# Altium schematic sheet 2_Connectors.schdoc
size 431 x 309 mm; Symbol: Sheet-Symbol_A4; Device: Sheet-Symbol_A4; Company: EasyEDA.com; Drawed: EasyEDA Pro; Reviewed: EasyEDA Pro; Version: V0.1; Page Size: A4; @Project Name: CM4-Nvme-NAS-main; @Page Count: 6; @Update Date: 2023-05-19; @Create Date: 2023-04-29; @Schematic Name: RaspberryPiNVMeNAS; Part Number: JLCPCB-002; @Page No: 5; @Page Name: Connectors
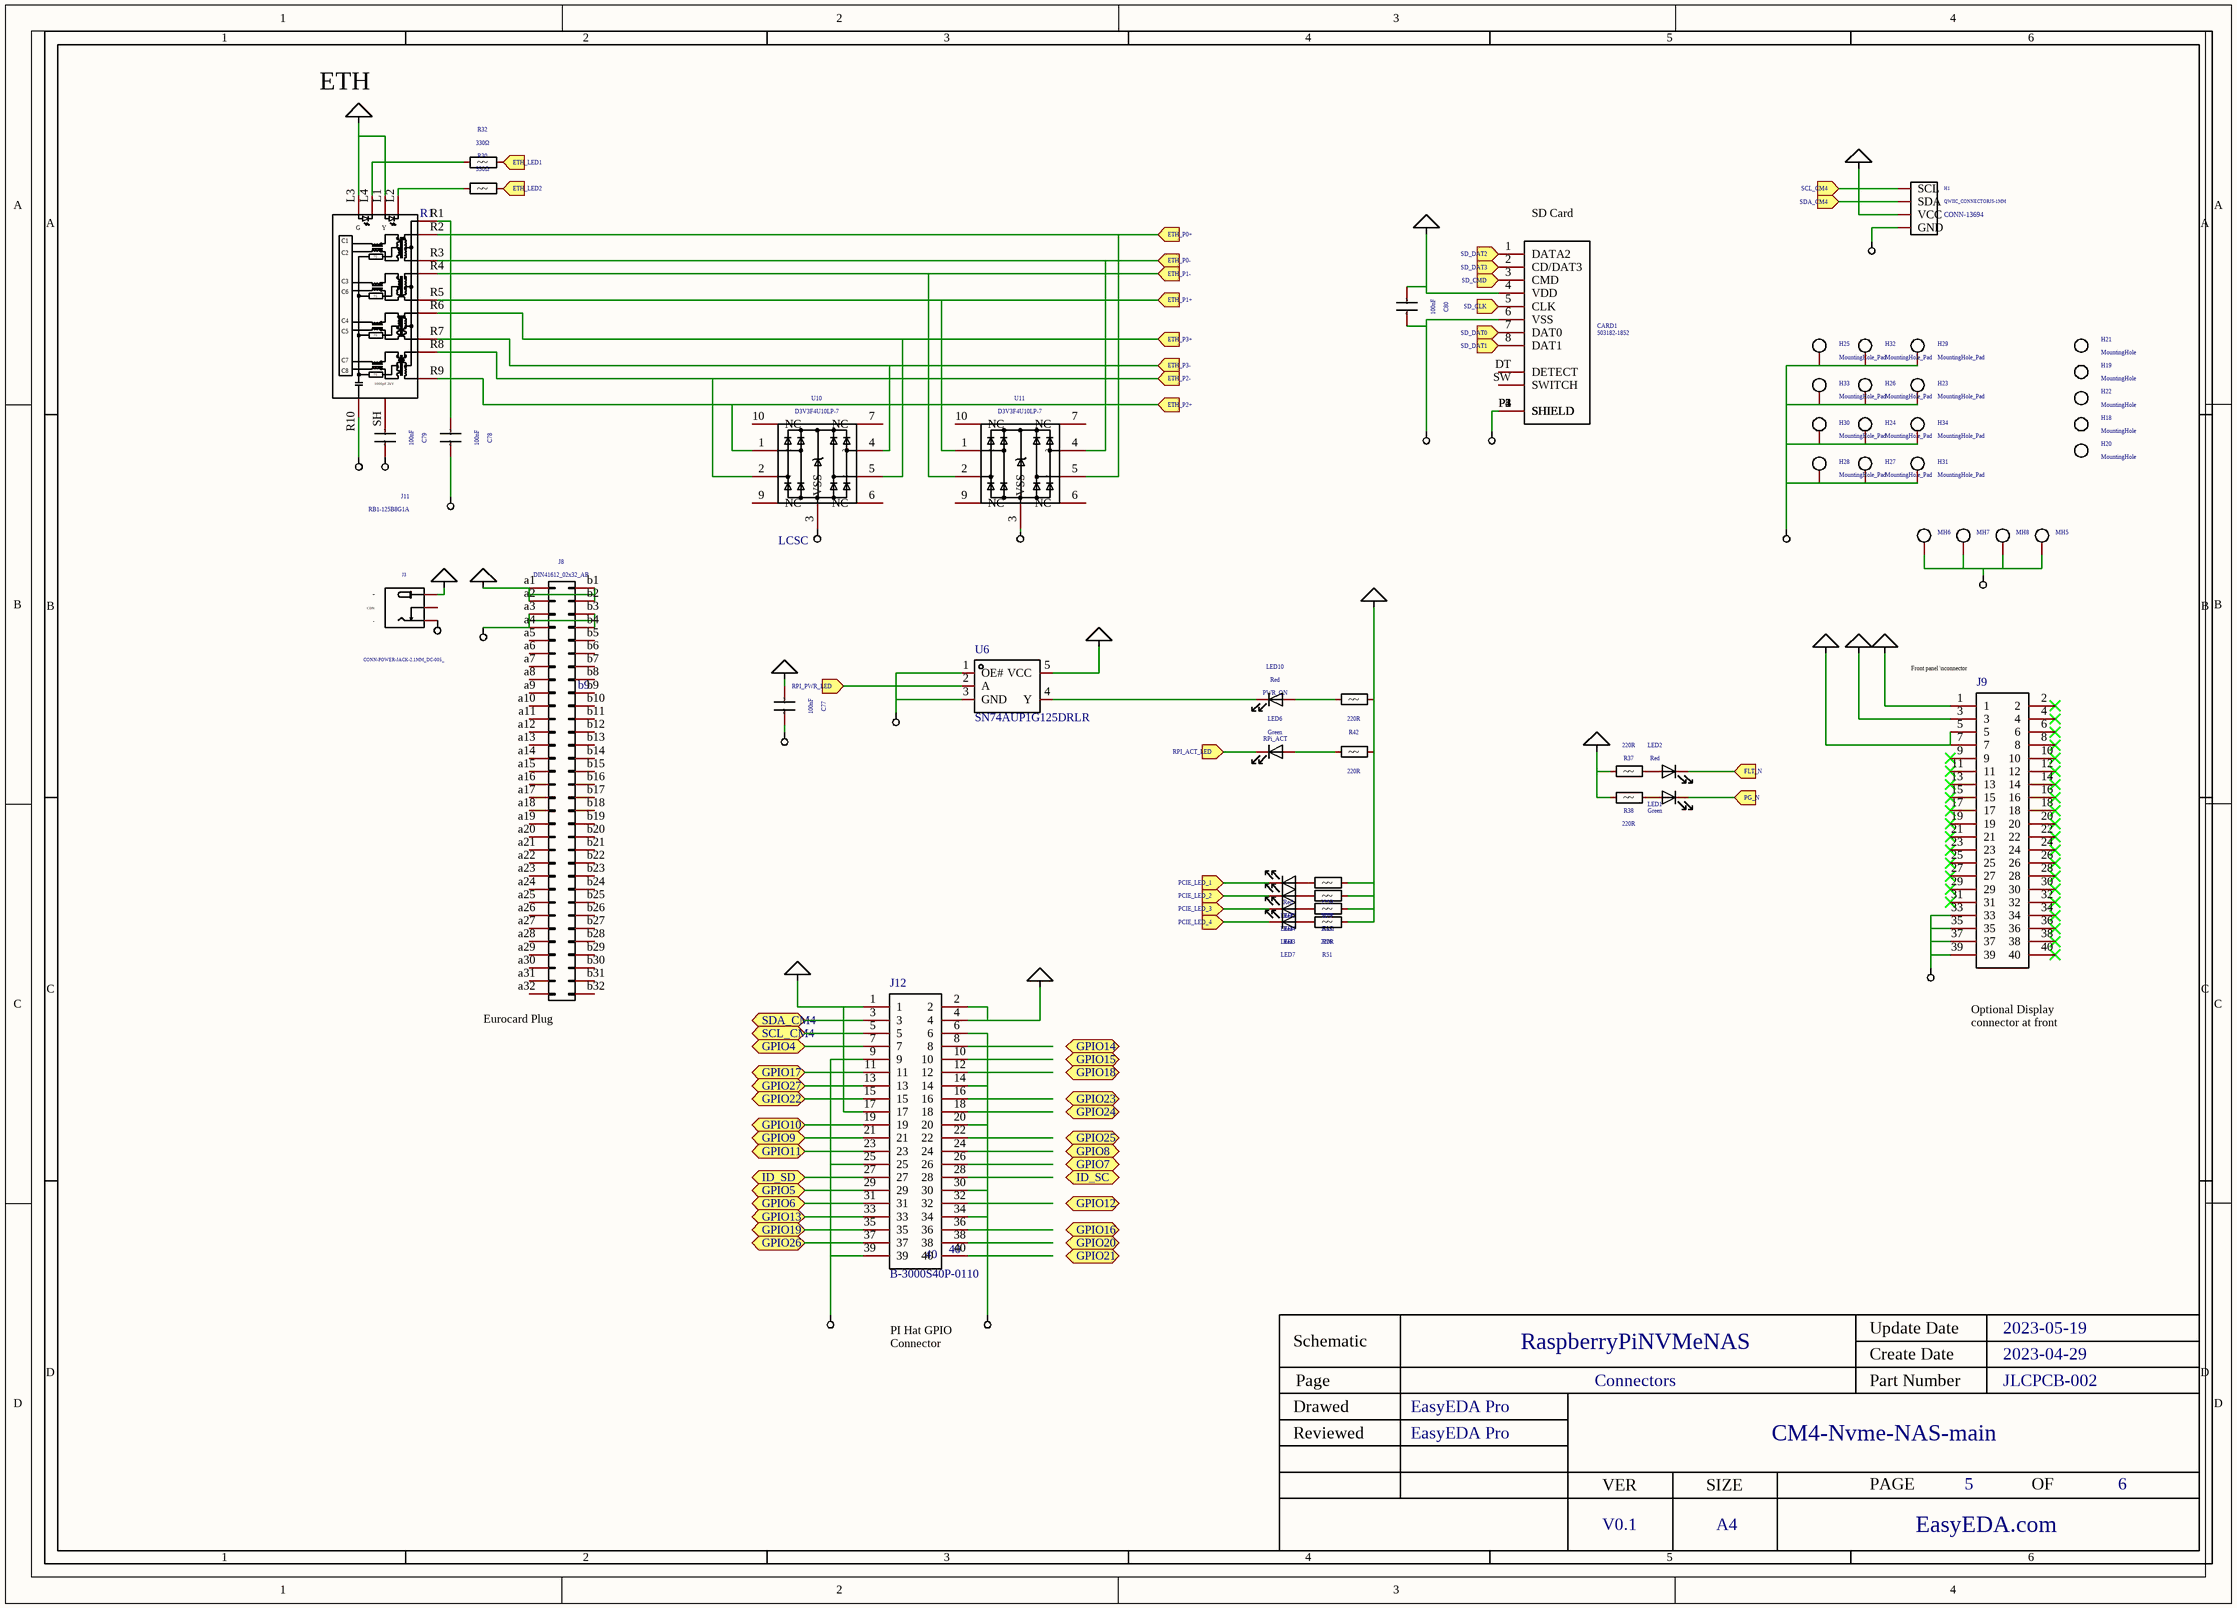
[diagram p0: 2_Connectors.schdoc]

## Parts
C77  100nF  [C0402]
C78  100nF  [C0402]
C79  100nF  [C0402]
C80  100nF  [C0402]
CARD1  value 503182-1852  [TF-SMD_503398-1892]  (hidden comment: 5033981892)
H1  value QWIIC_CONNECTORJS-1MM  Field4: CONN-13694  [HDR-SMD_4P-P2.00-H-M-W6.0-N]  (hidden comment: X4611WRS-04I-C40D28)
H18  value MountingHole  [MountingHole:MountingHole_2.7mm_M2.5]  (hidden comment: Mechanical_MountingHole)
H19  value MountingHole  [MountingHole:MountingHole_2.7mm_M2.5]  (hidden comment: Mechanical_MountingHole)
H20  value MountingHole  [MountingHole:MountingHole_2.7mm_M2.5]  (hidden comment: Mechanical_MountingHole)
H21  value MountingHole  [MountingHole:MountingHole_2.7mm_M2.5]  (hidden comment: Mechanical_MountingHole)
H22  value MountingHole  [MountingHole:MountingHole_2.7mm_M2.5]  (hidden comment: Mechanical_MountingHole)
H23  value MountingHole_Pad  [MountingHole:MountingHole_2.7mm_M2.5_Pad_TopOnly]  (hidden comment: Mechanical_MountingHole_Pad)
H24  value MountingHole_Pad  [MountingHole:MountingHole_2.7mm_M2.5_Pad_TopOnly]  (hidden comment: Mechanical_MountingHole_Pad)
H25  value MountingHole_Pad  [MountingHole:MountingHole_2.7mm_M2.5_Pad_TopOnly]  (hidden comment: Mechanical_MountingHole_Pad)
H26  value MountingHole_Pad  [MountingHole:MountingHole_2.7mm_M2.5_Pad_TopOnly]  (hidden comment: Mechanical_MountingHole_Pad)
H27  value MountingHole_Pad  [MountingHole:MountingHole_2.7mm_M2.5_Pad_TopOnly]  (hidden comment: Mechanical_MountingHole_Pad)
H28  value MountingHole_Pad  [MountingHole:MountingHole_2.7mm_M2.5_Pad_TopOnly]  (hidden comment: Mechanical_MountingHole_Pad)
H29  value MountingHole_Pad  [MountingHole:MountingHole_2.7mm_M2.5_Pad_TopOnly]  (hidden comment: Mechanical_MountingHole_Pad)
H30  value MountingHole_Pad  [MountingHole:MountingHole_2.7mm_M2.5_Pad_TopOnly]  (hidden comment: Mechanical_MountingHole_Pad)
H31  value MountingHole_Pad  [MountingHole:MountingHole_2.7mm_M2.5_Pad_TopOnly]  (hidden comment: Mechanical_MountingHole_Pad)
H32  value MountingHole_Pad  [MountingHole:MountingHole_2.7mm_M2.5_Pad_TopOnly]  (hidden comment: Mechanical_MountingHole_Pad)
H33  value MountingHole_Pad  [MountingHole:MountingHole_2.7mm_M2.5_Pad_TopOnly]  (hidden comment: Mechanical_MountingHole_Pad)
H34  value MountingHole_Pad  [MountingHole:MountingHole_2.7mm_M2.5_Pad_TopOnly]  (hidden comment: Mechanical_MountingHole_Pad)
J3  value CONN-POWER-JACK-2.1MM_DC-005_  [OPL_Connector:DCJ3P-11.6X9.6X7.0MM]  (hidden comment: OPL_Connector_CONN-POWER-JACK-2.1MM_DC-005_)
J8  value DIN41612_02x32_AB  NUMBER: b9  (hidden comment: Connector_DIN41612_02x32_AB)
J9  B-3000S40P-0110  [CONN-TH_300S-40P]  (value not drawn)
J11  value RB1-125B8G1A  NUMBER: R1  [RJ45-TH_HR911105A]  (hidden comment: HR911105A)
J12  NAME: 40  [CONN-TH_300S-40P]  (hidden comment: B-3000S40P-0110)
LED1  value Green  [LED0603-RD_RED]  (hidden comment: NCD0603R1)
LED2  value Red  [LED0603-RD_RED]  (hidden comment: NCD0603R1)
LED3  value Red  [LED0603-RD_RED]  (hidden comment: NCD0603R1)
LED4  value Red  [LED0603-RD_RED]  (hidden comment: NCD0603R1)
LED5  value Red  [LED0603-RD_RED]  (hidden comment: NCD0603R1)
LED6  value Green  [LED0603-RD_RED]  (hidden comment: RPi_ACT)
LED7  value Red  [LED0603-RD_RED]  (hidden comment: NCD0603R1)
LED10  value Red  [LED0603-RD_RED]  (hidden comment: PWR_ON)
MH5  Mechanical_MountingHole_Pad  (value not drawn)
MH6  Mechanical_MountingHole_Pad  (value not drawn)
MH7  Mechanical_MountingHole_Pad  (value not drawn)
MH8  Mechanical_MountingHole_Pad  (value not drawn)
R26  10kΩ  [R0402]
R30  330Ω  [R0402]
R32  330Ω  [R0402]
R37  value 220R  [Resistor_SMD:R_0402_1005Metric]  (hidden comment: Device_R)
R38  value 220R  [Resistor_SMD:R_0402_1005Metric]  (hidden comment: Device_R)
R39  value 220R  [Resistor_SMD:R_0402_1005Metric]  (hidden comment: Device_R)
R42  value 220R  [Resistor_SMD:R_0402_1005Metric]  (hidden comment: Device_R)
R51  value 220R  [Resistor_SMD:R_0402_1005Metric]  (hidden comment: Device_R)
R70  value 220R  [Resistor_SMD:R_0402_1005Metric]  (hidden comment: Device_R)
R73  value 220R  [Resistor_SMD:R_0402_1005Metric]  (hidden comment: Device_R)
U6  SN74AUP1G125DRLR  [SOT-553-5_L1.6-W1.2-P0.50-LS1.6-BL]
U10  value D3V3F4U10LP-7  Supplier: LCSC  [Package_DFN_QFN:Diodes_UDFN-10_1.0x2.5mm_P0.5mm]  (hidden comment: Power_Protection_D3V3XA4B10LP)
U11  value D3V3F4U10LP-7  [Package_DFN_QFN:Diodes_UDFN-10_1.0x2.5mm_P0.5mm]  (hidden comment: Power_Protection_D3V3XA4B10LP)

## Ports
ETH_LED1 (in), ETH_LED2 (in), ETH_P0+ (in), ETH_P0- (in), ETH_P1+ (in), ETH_P1- (in), ETH_P2+ (in), ETH_P2- (in), ETH_P3+ (in), ETH_P3- (in), FLT_N (in), GPIO4 (bidir), GPIO5 (bidir), GPIO6 (bidir), GPIO7 (bidir), GPIO8 (bidir), GPIO9 (bidir), GPIO10 (bidir), GPIO11 (bidir), GPIO12 (bidir), GPIO13 (bidir), GPIO14 (bidir), GPIO15 (bidir), GPIO16 (bidir), GPIO17 (bidir), GPIO18 (bidir), GPIO19 (bidir), GPIO20 (bidir), GPIO21 (bidir), GPIO22 (bidir), GPIO23 (bidir), GPIO24 (bidir), GPIO25 (bidir), GPIO26 (bidir), GPIO27 (bidir), ID_SC (bidir), ID_SD (bidir), PCIE_LED_1 (in), PCIE_LED_2 (in), PCIE_LED_3 (in), PCIE_LED_4 (in), PG_N (in), RPI_ACT_LED (in), RPI_PWR_LED (in), SCL_CM4 (bidir), SCL_CM4 (in), SD_CLK (in), SD_CMD (in), SD_DAT0 (in), SD_DAT1 (in), SD_DAT2 (in), SD_DAT3 (in), SDA_CM4 (bidir), SDA_CM4 (in)

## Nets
GND: J3.2(-) J8.a3(Pin_a3) J8.a4(Pin_a4) J8.b3(Pin_b3) J8.b4(Pin_b4) U11.3(VSS) U11.8(VSS)
POWER_+3.3V: C77.1 C80.1 CARD1.4(VDD) H1.2(VCC) J9.5 J9.7 J11.L1 J11.L3 J12.1 J12.17 R26.2 R39.2 R42.1 R51.2 R70.1 R73.2 U6.5(VCC)
POWER_+5V: J9.3 J12.2 J12.4
POWER_+12P: J3.1(+) J8.a1(Pin_a1) J8.a2(Pin_a2) J8.b1(Pin_b1) J8.b2(Pin_b2)
POWER_+12V: J9.1 R37.1 R38.1
POWER_GND: C77.2 C78.2 C79.2 C80.2 CARD1.6(VSS) CARD1.P1(SHIELD) CARD1.P2(SHIELD) CARD1.P3(SHIELD) CARD1.P4(SHIELD) CARD1.P5(SHIELD) H1.1(GND) H23.1 H24.1 H25.1 H26.1 H27.1 H28.1 H29.1 H30.1 H31.1 H32.1 H33.1 H34.1 J9.33 J9.35 J9.37 J9.39 J11.R10(GND) J12.6 J12.9 J12.14 J12.20 J12.25 J12.30 J12.34 J12.39 MH5.1 MH6.1 MH7.1 MH8.1 U6.1(OE#) U6.3(GND) U10.3(VSS) U10.8(VSS)
ETH_LED1: R32.2 ; port ETH_LED1
ETH_LED2: R30.2 ; port ETH_LED2
ETH_P0+: J11.R2(TD1+) U11.5 ; port ETH_P0+
ETH_P0-: J11.R3(TD1-) U11.4 ; port ETH_P0-
ETH_P1+: J11.R5(TD2-) U11.1 ; port ETH_P1+
ETH_P1-: J11.R4(TD2+) U11.2 ; port ETH_P1-
ETH_P2+: J11.R9(TD4-) U10.1 ; port ETH_P2+
ETH_P2-: J11.R8(TD4+) U10.2 ; port ETH_P2-
ETH_P3+: J11.R6(TD3+) U10.5 ; port ETH_P3+
ETH_P3-: J11.R7(TD3-) U10.4 ; port ETH_P3-
FLT_N: LED2.1(K) ; port FLT_N
GPIO4: J12.7 ; port GPIO4
GPIO5: J12.29 ; port GPIO5
GPIO6: J12.31 ; port GPIO6
GPIO9: J12.21 ; port GPIO9
GPIO10: J12.19 ; port GPIO10
GPIO11: J12.23 ; port GPIO11
GPIO13: J12.33 ; port GPIO13
GPIO17: J12.11 ; port GPIO17
GPIO19: J12.35 ; port GPIO19
GPIO22: J12.15 ; port GPIO22
GPIO26: J12.37 ; port GPIO26
GPIO27: J12.13 ; port GPIO27
ID_SD: J12.27 ; port ID_SD
PCIE_LED_1: LED5.1(K) ; port PCIE_LED_1
PCIE_LED_2: LED4.1(K) ; port PCIE_LED_2
PCIE_LED_3: LED3.1(K) ; port PCIE_LED_3
PCIE_LED_4: LED7.1(K) ; port PCIE_LED_4
PG_N: LED1.1(K) ; port PG_N
RPI_ACT_LED: LED6.1(K) ; port RPI_ACT_LED
RPI_PWR_LED: U6.2(A) ; port RPI_PWR_LED
SCL_CM4: H1.4(SCL) J12.5 ; port SCL_CM4
SD_CLK: CARD1.5(CLK) ; port SD_CLK
SD_CMD: CARD1.3(CMD) ; port SD_CMD
SD_DAT0: CARD1.7(DAT0) ; port SD_DAT0
SD_DAT1: CARD1.8(DAT1) ; port SD_DAT1
SD_DAT2: CARD1.1(DATA2) ; port SD_DAT2
SD_DAT3: CARD1.2(CD/DAT3) ; port SD_DAT3
SDA_CM4: H1.3(SDA) J12.3 ; port SDA_CM4
NetC78_1: C78.1 J11.R1(CT)
NetC79_1: C79.1 J11.SH
NetJ11_L2: J11.L2 R30.1
NetJ11_L4: J11.L4 R32.1
NetLED1_2: LED1.2(A) R38.2
NetLED2_2: LED2.2(A) R37.2
NetLED3_2: LED3.2(A) R26.1
NetLED4_2: LED4.2(A) R39.1
NetLED5_2: LED5.2(A) R73.1
NetLED6_2: LED6.2(A) R70.2
NetLED7_2: LED7.2(A) R51.1
NetLED10_1: LED10.1(K) U6.4(Y)
NetLED10_2: LED10.2(A) R42.2

Not connected (* = marked no-connect by the designer): CARD1 DT(DETECT) SW(SWITCH); J3 3(CDN); J8 a5(Pin_a5) a6(Pin_a6) a7(Pin_a7) a8(Pin_a8) a9(Pin_a9) a10(Pin_a10) a11(Pin_a11) a12(Pin_a12) a13(Pin_a13) a14(Pin_a14) a15(Pin_a15) a16(Pin_a16) a17(Pin_a17) a18(Pin_a18) a19(Pin_a19) a20(Pin_a20) a21(Pin_a21) a22(Pin_a22) a23(Pin_a23) a24(Pin_a24) a25(Pin_a25) a26(Pin_a26) a27(Pin_a27) a28(Pin_a28) a29(Pin_a29) a30(Pin_a30) a31(Pin_a31) a32(Pin_a32) b5(Pin_b5) b6(Pin_b6) b7(Pin_b7) b8(Pin_b8) b9(Pin_b9) b10(Pin_b10) b11(Pin_b11) b12(Pin_b12) b13(Pin_b13) b14(Pin_b14) b15(Pin_b15) b16(Pin_b16) b17(Pin_b17) b18(Pin_b18) b19(Pin_b19) b20(Pin_b20) b21(Pin_b21) b22(Pin_b22) b23(Pin_b23) b24(Pin_b24) b25(Pin_b25) b26(Pin_b26) b27(Pin_b27) b28(Pin_b28) b29(Pin_b29) b30(Pin_b30) b31(Pin_b31) b32(Pin_b32); J9 2* 4* 6* 8* 9* 10* 11* 12* 13* 14* 15* 16* 17* 18* 19* 20* 21* 22* 23* 24* 25* 26* 27* 28* 29* 30* 31* 32* 34* 36* 38* 40*; J12 8 10 12 16 18 22 24 26 28 32 36 38 40; U10 6(NC) 7(NC) 9(NC) 10(NC); U11 6(NC) 7(NC) 9(NC) 10(NC)

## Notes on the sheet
- ETH
- (near CARD1) SD Card
- (near J9) Front panel \nconnector
- (near J8) Eurocard Plug
- (near J9) Optional Display
  connector at front
- PI Hat GPIO
  Connector

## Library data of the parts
C77 C78 = CL05B104KO5NNNC: Capacitance: Tolerance:±10% Tolerance:±10% Voltage Rated: Temperature Coefficient:; Manufacturer: SAMSUNG(三星); Add into BOM: yes; Tolerance: ±10%; Origin Footprint: C_0402_1005Metric
C79 = CL05B104KO5NNNC: Capacitance: Tolerance:±10% Tolerance:±10% Voltage Rated: Temperature Coefficient:; Manufacturer: SAMSUNG(三星); Add into BOM: yes; Tolerance: ±10%; Origin Footprint: C_1206_3216Metric
C80 = CL05B104KO5NNNC: Capacitance: Tolerance:±10% Tolerance:±10% Voltage Rated: Temperature Coefficient:; Manufacturer: SAMSUNG(三星); Add into BOM: yes; Tolerance: ±10%; Origin Footprint: C_0805_2012Metric
CARD1 = 5033981892: Card Connection Mode:Self bomb Card Type:MicroSD卡(TF卡) Connector Type:Deck Maximum Body Height:- Operating Temperature Range:-25℃~+85℃ Operating Temperature Range:-25℃~+85℃; Manufacturer: MOLEX; Symbol: 503398-1892; Add into BOM: yes; Connector Type: Deck; Origin Footprint: MOLEX_503182-1852
H1 = X4611WRS-04I-C40D28: Pitch:2mm Number of Pins:4 Number of Rows: Pin Structure:1x4P Row Spacing:- Mounting Type:Surface Mount Circluar Pins/Square Pins:Square Pins Current Rating (Max):3A Voltage Rating (Max):250V Length of Mating Pin:4mm Insulation Height:2mm Length of End Co; Manufacturer: XKB Connectivity(中国星坤); Add into BOM: yes; Pitch: 2mm; Pin Structure: 1x4P; Current Rating (Max): 3A; Voltage Rating (Max): 250V; Welding Temperature (Max): 260℃; Origin Footprint: 1X04_1MM_RA
H18-H22 = Mechanical_MountingHole: Add into BOM: yes; Origin Footprint: MountingHole_2.7mm_M2.5
H23-H34 = Mechanical_MountingHole_Pad: Add into BOM: yes; Origin Footprint: MountingHole_2.7mm_M2.5_Pad_TopOnly
J3 = OPL_Connector_CONN-POWER-JACK-2.1MM_DC-005_: MPN: DC-005; Add into BOM: yes; Origin Footprint: DCJ3P-11.6X9.6X7.0MM
J8 = Connector_DIN41612_02x32_AB: Add into BOM: yes; NAME: Pin_b9; Pin Type: IN
J9 J12 = B-3000S40P-0110: Connector Type:简牛座 Pin Number in each Row:20 Structure:2x20P Number of Rows:2 Pitch:2.54mm Row Spacing:2.54mm Holder Type:Straight Contact Material:Brass Contact Plating:Gold; Manufacturer: Ckmtw(灿科盟); Symbol: 300S-40P; Add into BOM: yes; Connector Type: 简牛座; Pin Number in each Row: 20; Structure: 2x20P; Pitch: 2.54mm
J11 = HR911105A_C12074: Connector Type:RJReceptacle USOC Codes:RJ45 Number of Ports:1 Ratings:- Shielding:- LED:WithLED; Manufacturer: HANRUN(汉仁); Add into BOM: yes; USOC Codes: RJ45; Number of Ports: 1; Origin Footprint: RJ45_UDE_RB1-125B8G1A; NAME: CT; Pin Type: IN
LED1-LED7 LED10 = NCD0603R1_C84263: Emitted Color:红灯; Manufacturer: 国星光电; Symbol: FC-DA1608HRK-620D; Add into BOM: yes; Emitted Color: 红灯; Origin Footprint: LED_0603_1608Metric
MH5-MH8 = Mechanical_MountingHole_Pad: Add into BOM: yes
R26 = 0402WGF1002TCE: Type:Thick Film Resistors Resistance: Tolerance:±1% Tolerance:±1% Power(Watts): Temperature Coefficient:±100ppm/℃ Temperature Coefficient:±100ppm/℃ Overload Voltage (Max): Operating Temperature Range:-55℃~+155℃ Operating Temperature Range:-55℃~+155℃; Manufacturer: UNI-ROYAL(厚声); Add into BOM: yes; Tolerance: ±1%; Origin Footprint: R_0402_1005Metric
R30 R32 = RC0402JR-07330RL: Type:Thick Film Resistors Resistance: Tolerance:±5% Tolerance:±5% Power(Watts): Temperature Coefficient:±100ppm/℃ Temperature Coefficient:±100ppm/℃ Overload Voltage (Max): Operating Temperature Range:-55℃~+155℃ Operating Temperature Range:-55℃~+155℃; Manufacturer: YAGEO(国巨); Add into BOM: yes; Tolerance: ±5%; Origin Footprint: R_0402_1005Metric
R37-R39 R42 R51 R70 R73 = Device_R: Add into BOM: yes; Origin Footprint: R_0402_1005Metric
U6 = SN74AUP1G125DRLR: Type:Buffers，非反相 Supply Voltage:0.8V~3.6V Supply Voltage:0.8V~3.6V Input type:- output type:Tri-State Current-OutputLow:4mA Current-OutputHigh:4mA Operating temperature:-40℃~+85℃ Operating temperature:-40℃~+85℃; Manufacturer: TI(德州仪器); Add into BOM: yes; Current-OutputLow: 4mA
U10 U11 = Power_Protection_D3V3XA4B10LP: Add into BOM: yes; Origin Footprint: Diodes_UDFN-10_1.0x2.5mm_P0.5mm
